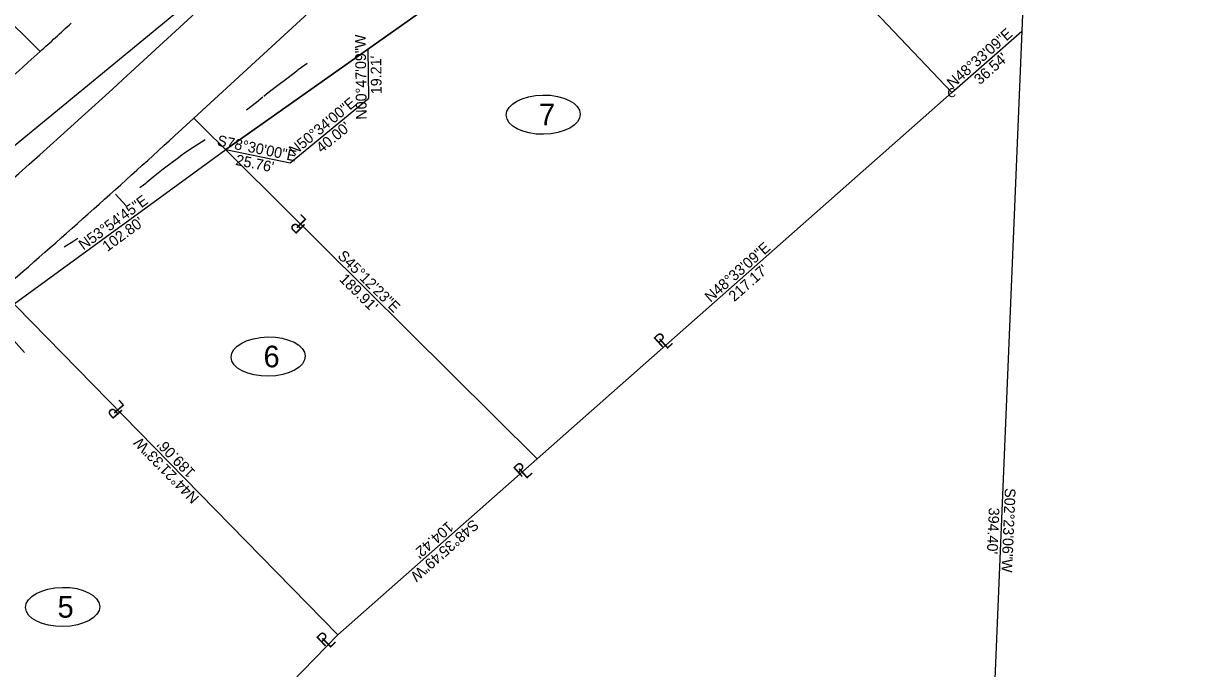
# Model space of a CAD drawing. Extents: x 1145508 to 2262867, y -3126236 to 2021677.
# Drawn here: x 1147204 to 1147660.6, y 2016959.7 to 2017213 of the extents above; entities that cross this region are included whole.
import ezdxf

# ---------------------------------------------------------------- set-up
doc = ezdxf.new("R2010")
doc.units = 0
for name, color, linetype in [('Default', 7, 'Continuous'), ('DSN_RDWY_Const Limits', 7, 'Continuous'), ('DSN_ROW_Annotation', 7, 'Continuous'), ('DSN_ROW_Esmnt', 7, 'Continuous'), ('DSN_ROW_Line', 7, 'Continuous'), ('DSN_ROW_Line-Annotation', 7, 'Continuous'), ('DSN_ROW_Prop-Line', 7, 'Continuous'), ('DSN_ROW_Prop-Line-Annotation', 7, 'Continuous'), ('E_Const Align', 7, 'Continuous'), ('EX_PRIMARY_CTL', 7, 'Continuous'), ('EX_QSECTION', 7, 'Continuous'), ('EX_ROW', 7, 'Continuous'), ('EX_ROW_ANNOT', 7, 'Continuous'), ('EX_SIGN', 7, 'Continuous')]:
    doc.layers.add(name, color=color, linetype=linetype)

msp = doc.modelspace()

# ---------------------------------------------------------------- linework, layer by layer
at = {"layer": 'Default'}
msp.add_line((1147359.68, 2017298.15), (1147243.01, 2017190.89), dxfattribs=at)
msp.add_arc((1145304.01, 2019299.75), 2864.79, 309.07734, 312.59711, dxfattribs=at)
at = {"layer": 'DSN_RDWY_Const Limits'}
for points in [[(1147298.37, 2017184.39), (1147299.4, 2017185.25), (1147299.98, 2017185.69), (1147301.18, 2017186.62), (1147303.37, 2017188.3), (1147307.35, 2017191.32), (1147311.34, 2017194.35), (1147311.91, 2017194.77), (1147313.12, 2017195.69), (1147315.36, 2017197.33)], [(1147291.58, 2017179.01), (1147295.55, 2017182.06), (1147297.99, 2017184.08)], [(1147249.77, 2017148.48), (1147251.1, 2017149.52), (1147252.02, 2017150.24), (1147252.62, 2017150.73), (1147254.99, 2017152.66), (1147258.87, 2017155.81), (1147262.86, 2017158.83), (1147263.82, 2017159.55), (1147264.38, 2017159.96), (1147266.87, 2017161.83), (1147271.09, 2017164.58), (1147275.29, 2017167.33)], [(1147220.02, 2017125.29), (1147223.81, 2017127.61), (1147225.36, 2017128.68)]]:
    msp.add_lwpolyline(points, dxfattribs=at)
at = {"layer": 'DSN_ROW_Esmnt'}
for p, q in [((1147339.57, 2017183.64), (1147339.31, 2017202.85)), ((1147308.67, 2017158.23), (1147339.57, 2017183.64)), ((1147283.43, 2017163.37), (1147308.67, 2017158.23))]:
    msp.add_line(p, q, dxfattribs=at)
at = {"layer": 'DSN_ROW_Line'}
for p, q in [((1147466.71, 2017292.88), (1147283.43, 2017163.37)), ((1147283.43, 2017163.37), (1147466.71, 2017292.88)), ((1147200.36, 2017102.81), (1147283.43, 2017163.37))]:
    msp.add_line(p, q, dxfattribs=at)
at = {"layer": 'DSN_ROW_Line-Annotation'}
for centre in [(1147408.07, 2017177.11), (1147300.09, 2017082.16), (1147219.41, 2016983.91)]:
    msp.add_ellipse(centre, major_axis=(14.54, 0.23), ratio=0.529773, dxfattribs=at)
at = {"layer": 'DSN_ROW_Prop-Line'}
for p, q in [((1147083.32, 2017328.61), (1147210.54, 2017201.84)), ((1147568.47, 2017185.74), (1147466.71, 2017292.88)), ((1147568.47, 2017185.74), (1147595.86, 2017209.92)), ((1147405.69, 2017041.99), (1147568.47, 2017185.74)), ((1147270.92, 2017175.79), (1147405.69, 2017041.99)), ((1147327.37, 2016972.93), (1147195.18, 2017108.11)), ((1147405.69, 2017041.99), (1147327.37, 2016972.93)), ((1147253.2, 2016896.95), (1147327.37, 2016972.93))]:
    msp.add_line(p, q, dxfattribs=at)
at = {"layer": 'E_Const Align'}
msp.add_line((1146840, 2016868.61), (1147825.51, 2017679.08), dxfattribs=at)
at = {"layer": 'EX_QSECTION'}
for p, q in [((1147602.14, 2017360.88), (1147595.86, 2017209.92)), ((1147595.86, 2017209.92), (1147579.44, 2016815.87))]:
    msp.add_line(p, q, dxfattribs=at)
at = {"layer": 'EX_ROW'}
for p, q in [((1147270.92, 2017175.79), (1147379.84, 2017275.93)), ((1147263.32, 2017168.8), (1147270.92, 2017175.79))]:
    msp.add_line(p, q, dxfattribs=at)
for radius, start, end in [(2834.79, 312.2638, 312.59711), (2834.79, 310.25076, 312.2638), (2894.79, 310.79095, 312.59711)]:
    msp.add_arc((1145304.01, 2019299.75), radius, start, end, dxfattribs=at)
at = {"layer": 'EX_SIGN'}
for p, q in [((1147240.1, 2017145.95), (1147244.35, 2017141.37)), ((1147204.5, 2017083.82), (1147191.03, 2017098.68))]:
    msp.add_line(p, q, dxfattribs=at)

# ---------------------------------------------------------------- texts
at = {"layer": 'DSN_ROW_Annotation'}
for s, rotation, p in [('N00°47\'09"W', 90.7857, (1147338.79, 2017175.17)), ('N48°33\'09"E', 41.4474, (1147568.78, 2017187.21)), ("19.21'", 90.7857, (1147344.65, 2017185.16)), ("36.54'", 41.4474, (1147579.43, 2017188.61)), ('N50°34\'00"E', 39.4333, (1147310.38, 2017160.8)), ("40.00'", 39.4333, (1147321.07, 2017161.82)), ('S78°30\'00"E', 348.5001, (1147279.81, 2017165.02)), ("25.76'", 348.5001, (1147287.05, 2017157.43)), ('N53°54\'45"E', 36.0874, (1147227.58, 2017123.77)), ("102.80'", 36.0874, (1147236.93, 2017123.16)), ('N48°33\'09"E', 41.4474, (1147473.7, 2017103.25)), ('S45°12\'23"E', 315.2063, (1147327.04, 2017121.34)), ("217.17'", 41.4474, (1147483.06, 2017103.51)), ("189.91'", 315.2063, (1147327.71, 2017112.22)), ('N44°21\'33"W', 134.3591, (1147273.26, 2017026.97)), ("189.06'", 134.3591, (1147271.81, 2017037.04)), ('S48°35\'49"W', 221.403, (1147380.45, 2017018.54)), ("104.42'", 221.403, (1147370.55, 2017017.8))]:
    msp.add_text(s, height=4.2, rotation=rotation, dxfattribs=at).set_placement(p)
at = {"layer": 'DSN_ROW_Line-Annotation'}
for s, p in [('7', (1147406.39, 2017172.91)), ('6', (1147298.27, 2017077.96)), ('5', (1147217.42, 2016979.7))]:
    msp.add_text(s, height=8.5, dxfattribs=at).set_placement(p)
at = {"layer": 'DSN_ROW_Prop-Line-Annotation'}
for s, rotation, p in [('L', 135.1131, (1147315.49, 2017135.62)), ('P', 135.1131, (1147314.97, 2017133.44)), ('P', 42.2511, (1147454.27, 2017085.44)), ('L', 42.2511, (1147456.42, 2017084.81)), ('L', 130.8619, (1147244.01, 2017062.66)), ('P', 130.8619, (1147243.32, 2017060.52)), ('P', 42.2511, (1147399.16, 2017034.54)), ('L', 42.2511, (1147401.31, 2017033.9)), ('P', 44.3119, (1147322.01, 2016968.04)), ('L', 44.3119, (1147324.19, 2016967.48))]:
    msp.add_text(s, height=5, rotation=rotation, dxfattribs=at).set_placement(p)
at = {"layer": 'EX_PRIMARY_CTL'}
msp.add_text('C', height=3.5, dxfattribs=at).set_placement((1147566.72, 2017183.99))
at = {"layer": 'EX_ROW_ANNOT'}
for s, p in [('S02°23\'06"W', (1147589.29, 2017030.61)), ('S02°23\'06"W', (1147589.29, 2017030.61)), ("394.40'", (1147582.96, 2017022.96)), ("394.40'", (1147582.96, 2017022.96))]:
    msp.add_text(s, height=4.2, rotation=267.6149, dxfattribs=at).set_placement(p)

doc.saveas('drawing.dxf')
